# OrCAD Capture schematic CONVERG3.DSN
size A
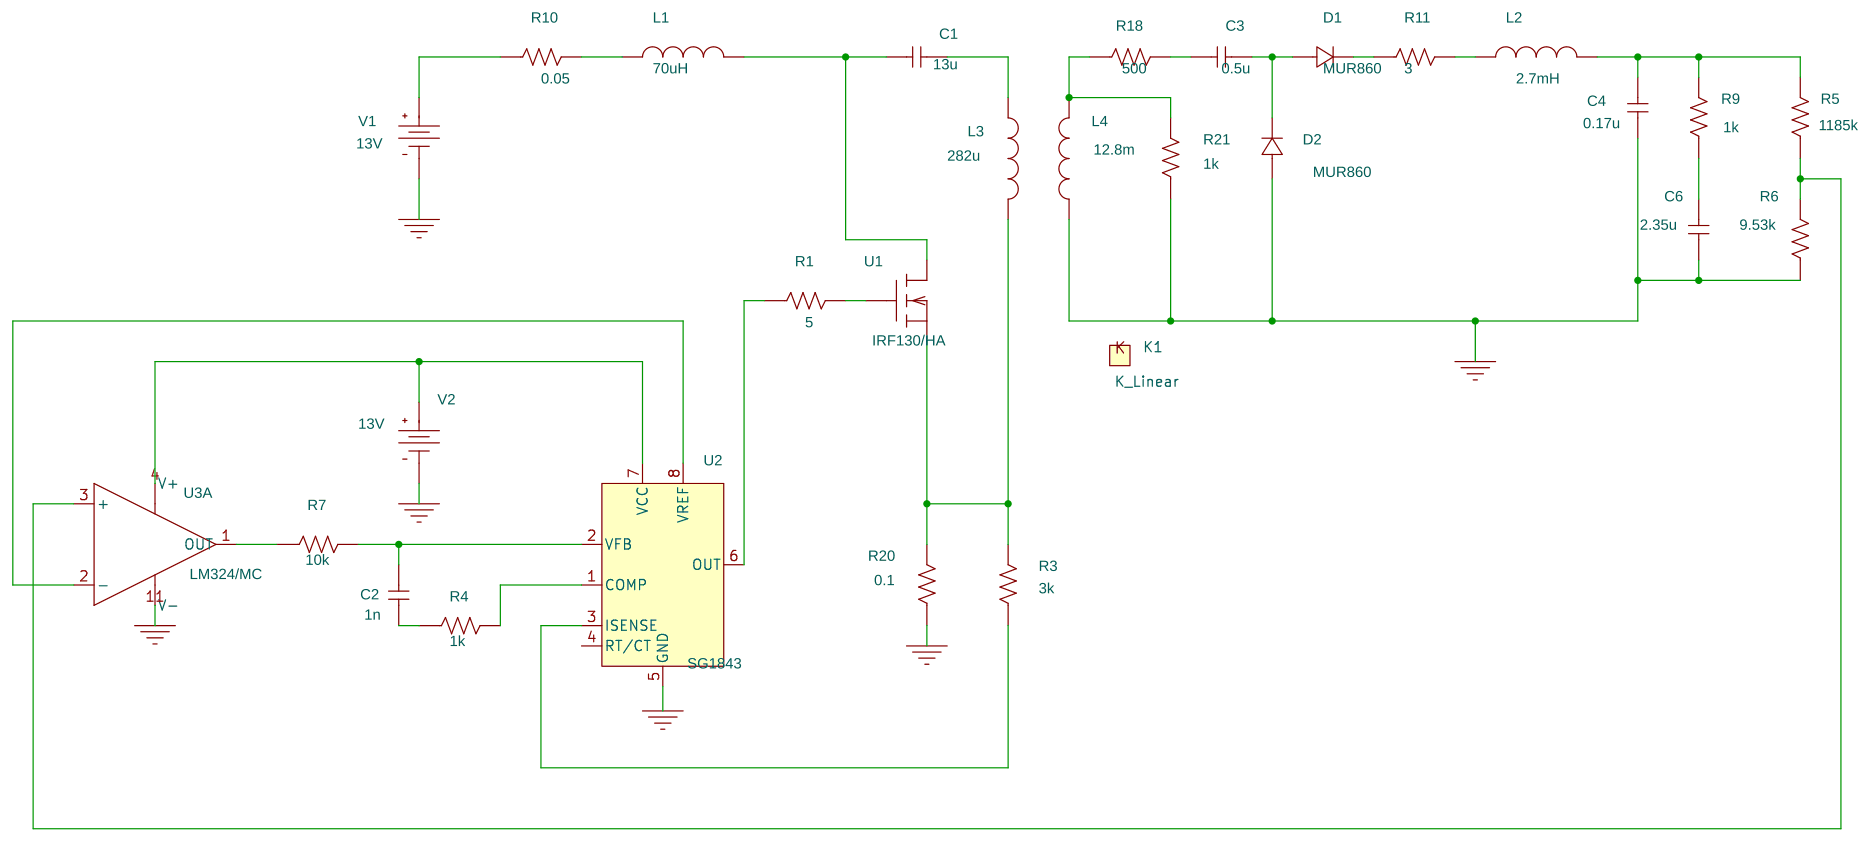
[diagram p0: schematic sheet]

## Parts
C1  13u  [CK05]
C2  1n  [CK05]
C3  0.5u  [CK05]
C4  0.17u  [CK05]
C6  2.35u  [CK05]
D1  MUR860  [TO220AC]
D2  MUR860  [TO220AC]
K1  K_Linear
L1  70uH  [L2012C]
L2  2.7mH  [L2012C]
L3  282u  [L2012C]
L4  12.8m  [L2012C]
R1  5  [RC05]
R3  3k  [RC05]
R4  1k  [RC05]
R5  1185k  [RC05]
R6  9.53k  [RC05]
R7  10k  [RC05]
R9  1k  [RC05]
R10  0.05  [RC05]
R11  3  [RC05]
R18  500  [RC05]
R20  0.1  [RC05]
R21  1k  [RC05]
U1  IRF130/HA  [TO-204AA]
U2  SG1843  [DIP.100/8/W.300/L.450]
U3  LM324/MC  [DIP.100/14/W.300/L.800]  (section A)
V1  VDC
V2  VDC

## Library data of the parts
C1-C4 C6 = C
D1 D2 = MUR860
K1 = K_Linear: L1: L3; L2: L4
L1-L4 = L
R1 R3-R7 R9-R11 R18 R20 R21 = R
U1 = IRF130_HA
U2 = SG1843
U3 = LM324_MC
V1 V2 = VDC: DC: 13V

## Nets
0: C4.1 C6.1 D2.3(1) L4.1 R6.1 R20.1 R21.1 U2.5(GND) U3.11(V-) V1.1(-) V2.1(-)
N00088: R10.1 V1.0(+)
N00095: L1.1 R10.2
N00098: C1.1 L1.2 U1.2(d)
N00101: C1.2 L3.1
N00111: L4.2 R18.1 R21.2
N00115: C3.1 R18.2
N00125: C3.2 D1.3(1) D2.1(2)
N00132: D1.1(2) R11.1
N00135: L2.1 R11.2
N00157: C4.2 L2.2 R5.2 R9.2
N00201: R1.1 U2.6(OUT)
N00213: R1.2 U1.1(g)
N00239: L3.2 R3.2 R20.2 U1.3(s)
N00274: R3.1 U2.3(ISENSE)
N00443: R4.2 U2.1(COMP)
N00450: C2.1 R4.1
N00453: C2.2 R7.2 U2.2(VFB)
N00465: R7.1 U3.1(OUT)
N00508: U2.8(VREF) U3.2(-)
N00585: U2.7(VCC) U3.4(V+) V2.0(+)
N00610: R5.1 R6.2 U3.3(+)
N00855: C6.2 R9.1

Not connected (* = marked no-connect by the designer): U2 4(RT/CT)
